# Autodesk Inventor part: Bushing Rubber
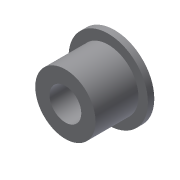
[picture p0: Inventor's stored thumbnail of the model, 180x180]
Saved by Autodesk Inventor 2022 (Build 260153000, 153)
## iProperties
Created: 2010-03
Part Number: Bushing Rubber
Document SubType Name: Modeling
Designer: bhakira
Density: 1 g/cm^3
Material: Generic
Appearance: Default
Author: bhakira
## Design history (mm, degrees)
sketch "Sketch1"
  geometry: L1 (25, 31)-(25, 27); L2 (25, 27)-(19, 27); L3 (19, 27)-(19, 0); L4 (19, 0)-(0, 0); L5 (0, 0)-(0, 31); L6 (0, 31)-(25, 31); 1 further point
  constraints: 12 end point, 1 coincident, 1 other
  dimensions: "d1" = 50 diameter of L1 L5; "d2" = 38 diameter of L3 L5; "d3" = 4 distance of L1.start L1.end; "d4" = 27 distance between parallel lines of L4 L2
revolve "Revolution1" sketch "Sketch1" stored, may be unused: angle "d5" = 90 deg
hole "Hole1" diameter "d8" = 20; stored, may be unused: countersink angle "d12" = 82 deg, drill point angle "d14" = 118 deg; dims "d6" = 10, "d7" = 10, "d9" = 6, "d10" = 34.925, "d11" = 2, "d13" = 8
body "Solid1"
